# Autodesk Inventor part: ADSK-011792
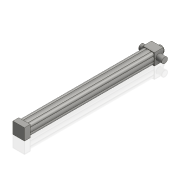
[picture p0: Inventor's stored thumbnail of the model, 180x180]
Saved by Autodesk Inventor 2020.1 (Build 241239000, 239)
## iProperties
Created: 1999-11
Part Number: ADSK-011792
Material: Aluminum
Document SubType Name: Modeling
Designer: kcovelli
Density: 2.71 g/cm^3
Appearance: Steel
Mass: 1066.22 g
Surface Area: 2160.37 cm^2
Volume: 393.437 cm^3
Control State: 0
Master: False
Checked Out: False
Shininess: 0.0
Length Units: 11269
Angle Units: 11279
Time Units: 11290
Mass Units: 11283
Length Display Precision: 3
Angle Display Precision: 2
Compacted: True
Dimensions: 50x615,5x100 mm
Mass: 1,066 kg
DocNumber: ADSK-011792.ipt
Folder: 01 - Themengebiete\Simplification\01 - Packaging machine\
VDS_Category: 3D Komponenten
VLT_Material: Aluminum
Density: 0.0
Volumn: 0.0
Area: 0.0
PropertySet Name: Model Information
Author: kcovelli
Revision Number: -
Title: cylinder
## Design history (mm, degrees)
node "Extrusion1" dims "d0" = 38, "d1" = 0
  sketch "Sketch1"
    geometry: L1 (-25, 25)-(25, 25); L2 (25, 25)-(25, -25); L3 (25, -25)-(-25, -25); L4 (-25, -25)-(-25, 25); 3 further points
    constraints: 8 end point, 2 midpoint, 2 parallel, 1 horizontal, 1 horizontal alignment, 1 perpendicular, 1 vertical alignment
    dimensions: "d3" = 50 distance of L1.end L2.end (= d64); "d64" = 50 distance between parallel lines of L2 L4
node "Extrusion3" dims "d24" = 536.5, "d25" = 0
  sketch "Sketch5"
    geometry: L1 (-25, -25)-(-25, 25) reference; L2 (-25, 25)-(25, 25) reference; L3 (-15.026, 15.026)-(15.026, -15.026); L4 (15.026, 15.026)-(-15.026, -15.026); L5 (0, 0)-(0, 21.25); C1 r 8 at (-15.026, 15.026); C2 r 8 at (15.026, 15.026); C3 r 8 at (-15.026, -15.026); C4 r 8 at (15.026, -15.026); C5 r 23.75 at (0, 0); A1 r 21.25 centre (0, 0) between (-15.026, 15.026) and (15.026, 15.026); 2 further points
    constraints: 6 centre point, 6 end point, 4 midpoint, 3 point on circle, 2 coincident, 1 horizontal alignment, 1 perpendicular, 1 vertical, 1 vertical alignment
    dimensions: "d18" = 16 diameter of C3; "d19" = 16 diameter of C2 (= d18); "d20" = 16 diameter of C4 (= d18); "d23" = 47.5 diameter of C5; "d73" = 45 deg angle of L5 L3; "d74" = 42.5 diameter of A1; "d75" = 16 diameter of C1 (= d18)
node "Shell1" dims "d26" = 3
node "Extrusion4" dims "d27" = 25, "d28" = 0
node "Extrusion9" dims "d52" = 16, "d53" = 0
  sketch "Sketch13"
    geometry: C1 r 14.25 at (0, 0)
    constraints: 1 centre point
    dimensions: "d76" = 28.5 diameter of C1
node "Extrusion10" dims "d55" = 76.2, "d56" = 0
  sketch "Sketch14"
    geometry: C1 r 14.25 at (0, 0) reference; C2 r 8 at (0, 0)
    constraints: 1 centre point, 1 coincident
    dimensions: "d54" = 16 diameter of C2
workplane "Work Plane4"
workplane "Arbeitsebene6"
  workplane "Work Plane5"
node "Extrusion11" dims "d71" = 101.6, "d72" = 0
  sketch "Sketch15"
    geometry: L1 (0, 0)-(38, 0) reference; L2 (0, 0)-(0, 50) reference; C1 r 12.5 at (19, 25); 2 further points
    constraints: 2 midpoint, 1 centre point, 1 horizontal alignment, 1 vertical alignment
    dimensions: "d70" = 25 diameter of C1
mirror "Spiegeln4"
node "Solide1"
node "Corps solides"
node "Corps surfaciques"
sketch "Sketch6"
  geometry: L1 (-25, -25)-(-25, 25) reference; L2 (-25, 25)-(25, 25) reference; L3 (25, 25)-(25, -25) reference; L4 (25, -25)-(-25, -25) reference
other parameters: "d67" = -25.4, "d68" = -25.4
